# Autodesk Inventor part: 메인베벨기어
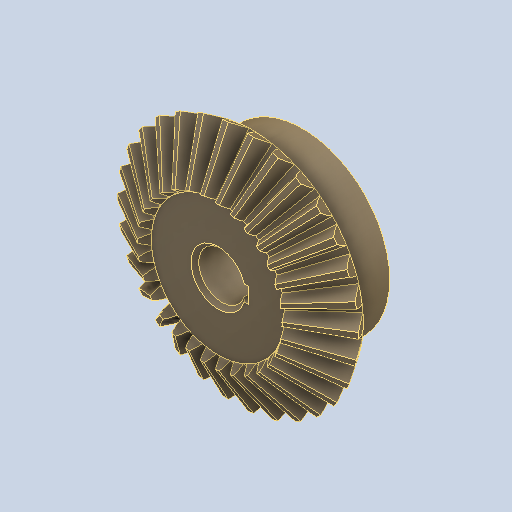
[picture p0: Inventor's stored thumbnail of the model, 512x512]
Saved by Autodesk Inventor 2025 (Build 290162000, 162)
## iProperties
Created: 2024-08
Part Number: 메인베벨기어
Material: 강철, 탄소
Document SubType Name: Modeling
Designer: rese9
Density: 7.87 g/cm^3
Appearance: 기본값
Author: jhkim
Sending System: Autodesk Inventor 2025
Preprocessor: ST-DEVELOPER v20
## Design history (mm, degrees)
feature "Solid1"
node "솔리드1"
